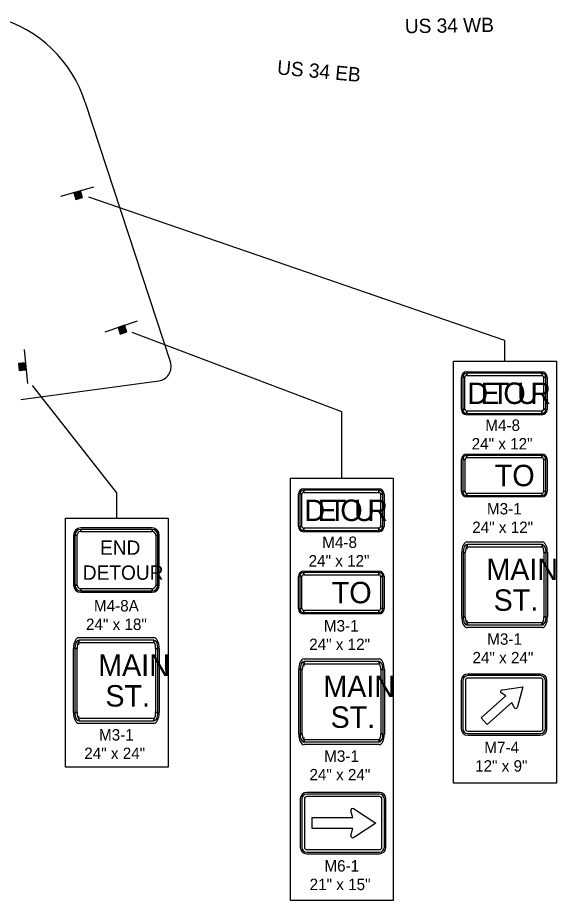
# Model space of a CAD drawing. Extents: x 10133 to 81668, y 6132 to 11018.
# Drawn here: x 11971 to 12349, y 8498 to 9117 of the extents above; entities that cross this region are included whole.
import ezdxf

# ---------------------------------------------------------------- set-up
doc = ezdxf.new("R2010")
doc.units = 0
for name, color, linetype in [('dsnTextFinalPlan', 7, 'Continuous'), ('Level 10', 7, 'Continuous'), ('Level 2', 7, 'Continuous'), ('Level 5', 7, 'Continuous')]:
    doc.layers.add(name, color=color, linetype=linetype)

msp = doc.modelspace()

# ---------------------------------------------------------------- linework, layer by layer
at = {"layer": 'dsnTextFinalPlan'}
for p, q in [((12001.09, 8991.94), (12024.18, 8998.48)), ((12015, 8995.5), (12010.31, 8994.18)), ((12010.37, 8993.94), (12015.07, 8995.27)), ((12015.13, 8995.05), (12010.44, 8993.72)), ((12010.5, 8993.5), (12015.19, 8994.83)), ((12015.25, 8994.64), (12010.55, 8993.31)), ((12010.6, 8993.14), (12015.29, 8994.47)), ((12015.37, 8994.18), (12010.68, 8992.85)), ((12010.74, 8992.63), (12015.44, 8993.96)), ((12015.49, 8993.77), (12010.79, 8992.46)), ((12010.87, 8992.18), (12015.57, 8993.5)), ((12015.66, 8993.19), (12010.96, 8991.86)), ((12011.07, 8991.5), (12015.76, 8992.83)), ((12015.81, 8992.64), (12011.11, 8991.33)), ((12011.22, 8990.96), (12015.91, 8992.28)), ((12015.96, 8992.1), (12011.27, 8990.77)), ((12011.35, 8990.51), (12016.04, 8991.84)), ((12016.09, 8991.65), (12011.4, 8990.32)), ((12011.47, 8990.05), (12016.17, 8991.38)), ((12032.17, 8896.87), (12054.89, 8904.6)), ((12045.88, 8901.15), (12041.26, 8899.58)), ((12041.34, 8899.35), (12045.96, 8900.92)), ((12046.03, 8900.7), (12041.41, 8899.13)), ((12041.49, 8898.91), (12046.1, 8900.49)), ((12046.17, 8900.3), (12041.55, 8898.73)), ((12041.61, 8898.56), (12046.23, 8900.13)), ((12046.32, 8899.85), (12041.7, 8898.28)), ((12041.78, 8898.06), (12046.39, 8899.63)), ((12046.46, 8899.45), (12041.84, 8897.89)), ((12041.93, 8897.61), (12046.55, 8899.18)), ((12046.65, 8898.87), (12042.04, 8897.3)), ((12042.16, 8896.95), (12046.77, 8898.52)), ((12046.84, 8898.33), (12042.22, 8896.78)), ((12042.34, 8896.42), (12046.96, 8897.98)), ((12047.02, 8897.81), (12042.4, 8896.23)), ((12042.49, 8895.97), (12047.11, 8897.54)), ((12047.17, 8897.36), (12042.55, 8895.78)), ((12042.64, 8895.52), (12047.26, 8897.09)), ((11975.3, 8884.55), (11977.56, 8860.65)), ((11971.57, 8874.67), (11972.03, 8869.82)), ((11972.3, 8869.84), (11971.84, 8874.7)), ((11972.04, 8874.72), (11972.5, 8869.86)), ((11972.77, 8869.89), (11972.32, 8874.74)), ((11972.51, 8874.76), (11972.95, 8869.91)), ((11973.33, 8869.94), (11972.89, 8874.8)), ((11973.07, 8874.82), (11973.52, 8869.96)), ((11973.9, 8870), (11973.44, 8874.85)), ((11973.77, 8874.88), (11974.22, 8870.03)), ((11974.5, 8870.05), (11974.06, 8874.91)), ((11974.24, 8874.93), (11974.7, 8870.07)), ((11974.93, 8870.09), (11974.47, 8874.95)), ((11974.76, 8874.98), (11975.22, 8870.12)), ((11975.4, 8870.14), (11974.94, 8874.99)), ((11975.13, 8875.01), (11975.59, 8870.16)), ((11975.82, 8870.18), (11975.36, 8875.03)), ((11975.59, 8875.05), (11976.05, 8870.2)), ((11976.29, 8870.22), (11975.84, 8875.08)), ((11972.93, 8849.28), (12069.69, 8862.39)), ((12337.44, 8656.85), (12286.47, 8656.85)), ((12281.89, 8652.27), (12281.89, 8618.48)), ((12342.02, 8618.48), (12342.02, 8652.27)), ((12286.47, 8613.9), (12337.44, 8613.9))]:
    msp.add_line(p, q, dxfattribs=at)
for points in [[(12018.16, 9057.63), (12018.16, 9057.63), (12077.85, 8875.41)], [(12312.56, 8876.29), (12312.56, 8890.73), (12020.7, 8991.36)], [(12198.2, 8794.21), (12198.2, 8840.64), (12051.02, 8896.35)], [(12040.25, 8766.11), (12040.25, 8784.03), (11981.11, 8859.25)], [(12319.03, 8633.29), (12317.4, 8636.8), (12300.08, 8621.52), (12295.92, 8626.23), (12313.25, 8641.51), (12309.95, 8643.54)], [(12310.74, 8645.71), (12325.1, 8647.78), (12321.24, 8633.81)]]:
    msp.add_lwpolyline(points, dxfattribs=at)
for points in [[(12014.92, 8995.77), (12010.2, 8994.43), (12011.54, 8989.71), (12016.26, 8991.05)], [(12045.79, 8901.41), (12041.14, 8899.83), (12042.72, 8895.18), (12047.37, 8896.77)], [(11976.57, 8870.25), (11976.11, 8875.14), (11971.22, 8874.67), (11971.68, 8869.79)], [(12276.52, 8876.29), (12348.59, 8876.29), (12348.59, 8580.2), (12276.52, 8580.2)], [(12276.52, 8876.29), (12348.59, 8876.29), (12348.59, 8580.2), (12276.52, 8580.2)], [(12162.17, 8794.21), (12234.23, 8794.21), (12234.23, 8498.11), (12162.17, 8498.11)], [(12162.17, 8794.21), (12234.23, 8794.21), (12234.23, 8498.11), (12162.17, 8498.11)], [(12004.21, 8766.11), (12076.28, 8766.11), (12076.28, 8591.52), (12004.21, 8591.52)], [(12004.21, 8766.11), (12076.28, 8766.11), (12076.28, 8591.52), (12004.21, 8591.52)]]:
    msp.add_lwpolyline(points, close=True, dxfattribs=at)
for centre, radius, start, end in [((11932.89, 9030.85), 89.37, 17.43569, 74.97168), ((12068.34, 8872.3), 10, 277.71379, 18.13661), ((12286.47, 8652.27), 4.58, 90, 180), ((12337.44, 8652.27), 4.58, 360, 90), ((12310.58, 8644.52), 1.16, 98.0346, 237.39274), ((12294.21, 8760.49), 115.96, 278.0346, 278.19506), ((12320.05, 8633.78), 1.14, 205.45459, 344.73406), ((12433.02, 8602.95), 115.96, 164.56669, 164.73406), ((12286.47, 8618.48), 4.58, 180, 270), ((12337.44, 8618.48), 4.58, 270, 0)]:
    msp.add_arc(centre, radius, start, end, dxfattribs=at)
at = {"layer": 'Level 10'}
for p, q in [((12285.73, 8868.78), (12338.34, 8868.78)), ((12285.73, 8866.28), (12285.73, 8867.84)), ((12338.34, 8867.84), (12338.34, 8866.28)), ((12281.97, 8842.48), (12281.97, 8865.03)), ((12282.91, 8865.03), (12284.48, 8865.03)), ((12339.6, 8865.03), (12341.16, 8865.03)), ((12342.1, 8865.03), (12342.1, 8842.48)), ((12284.48, 8842.48), (12282.91, 8842.48)), ((12285.73, 8839.66), (12285.73, 8841.23)), ((12338.34, 8841.23), (12338.34, 8839.66)), ((12341.16, 8842.48), (12339.6, 8842.48)), ((12338.34, 8838.72), (12285.73, 8838.72)), ((12285.78, 8811.1), (12338.39, 8811.1)), ((12285.78, 8808.59), (12285.78, 8810.16)), ((12338.39, 8810.16), (12338.39, 8808.59)), ((12282.02, 8784.79), (12282.02, 8807.34)), ((12282.96, 8807.34), (12284.52, 8807.34)), ((12339.64, 8807.34), (12341.21, 8807.34)), ((12342.15, 8807.34), (12342.15, 8784.79)), ((12171.38, 8786.7), (12223.99, 8786.7)), ((12171.38, 8784.19), (12171.38, 8785.76)), ((12223.99, 8785.76), (12223.99, 8784.19)), ((12284.52, 8784.79), (12282.96, 8784.79)), ((12341.21, 8784.79), (12339.64, 8784.79)), ((12167.62, 8760.39), (12167.62, 8782.94)), ((12168.56, 8782.94), (12170.12, 8782.94)), ((12225.24, 8782.94), (12226.81, 8782.94)), ((12227.75, 8782.94), (12227.75, 8760.39)), ((12285.78, 8781.97), (12285.78, 8783.54)), ((12338.39, 8781.03), (12285.78, 8781.03)), ((12338.39, 8783.54), (12338.39, 8781.97)), ((12170.12, 8760.39), (12168.56, 8760.39)), ((12226.81, 8760.39), (12225.24, 8760.39)), ((12009.94, 8754.26), (12009.94, 8719.19)), ((12010.94, 8754.26), (12010.94, 8719.19)), ((12012.44, 8754.26), (12010.94, 8754.26)), ((12010.94, 8754.26), (12012.44, 8754.26)), ((12012.44, 8719.19), (12012.44, 8754.26)), ((12065.06, 8759.27), (12014.95, 8759.27)), ((12014.95, 8756.77), (12014.95, 8758.27)), ((12065.06, 8758.27), (12014.95, 8758.27)), ((12014.95, 8758.27), (12014.95, 8756.77)), ((12014.95, 8756.77), (12065.06, 8756.77)), ((12065.06, 8756.77), (12065.06, 8758.27)), ((12065.06, 8758.27), (12065.06, 8756.77)), ((12067.56, 8754.26), (12069.06, 8754.26)), ((12067.56, 8754.26), (12067.56, 8719.19)), ((12069.06, 8754.26), (12067.56, 8754.26)), ((12069.06, 8719.19), (12069.06, 8754.26)), ((12070.07, 8719.19), (12070.07, 8754.26)), ((12171.38, 8757.57), (12171.38, 8759.14)), ((12223.99, 8756.63), (12171.38, 8756.63)), ((12223.99, 8759.14), (12223.99, 8757.57)), ((12285.97, 8749.51), (12338.58, 8749.51)), ((12285.97, 8744.5), (12285.97, 8747.64)), ((12338.58, 8747.64), (12338.58, 8746.07)), ((12282.21, 8696.9), (12282.21, 8742)), ((12283.15, 8742), (12284.71, 8742)), ((12339.83, 8742), (12341.4, 8742)), ((12342.34, 8742), (12342.34, 8696.9)), ((12171.42, 8729.01), (12224.03, 8729.01)), ((12167.66, 8702.7), (12167.66, 8725.25)), ((12168.6, 8725.25), (12170.17, 8725.25)), ((12171.42, 8726.5), (12171.42, 8728.07)), ((12224.03, 8728.07), (12224.03, 8726.5)), ((12225.29, 8725.25), (12226.85, 8725.25)), ((12227.79, 8725.25), (12227.79, 8702.7)), ((12010.94, 8719.19), (12012.44, 8719.19)), ((12012.44, 8719.19), (12010.94, 8719.19)), ((12065.06, 8716.68), (12014.95, 8716.68)), ((12014.95, 8716.68), (12014.95, 8715.18)), ((12014.95, 8715.18), (12014.95, 8716.68)), ((12065.06, 8716.68), (12065.06, 8715.18)), ((12065.06, 8715.18), (12065.06, 8716.68)), ((12067.56, 8719.19), (12069.06, 8719.19)), ((12069.06, 8719.19), (12067.56, 8719.19)), ((12014.95, 8715.18), (12065.06, 8715.18)), ((12014.95, 8714.18), (12065.06, 8714.18)), ((12170.17, 8702.7), (12168.6, 8702.7)), ((12171.42, 8699.89), (12171.42, 8701.45)), ((12224.03, 8698.95), (12171.42, 8698.95)), ((12224.03, 8701.45), (12224.03, 8699.89)), ((12226.85, 8702.7), (12225.29, 8702.7)), ((12284.71, 8696.9), (12283.15, 8696.9)), ((12285.97, 8691.27), (12285.97, 8694.4)), ((12338.58, 8692.83), (12338.58, 8691.27)), ((12341.4, 8696.9), (12339.83, 8696.9)), ((12338.58, 8689.39), (12285.97, 8689.39)), ((12013.66, 8682.37), (12066.27, 8682.37)), ((12013.66, 8677.36), (12013.66, 8680.49)), ((12066.27, 8680.49), (12066.27, 8678.92)), ((12009.9, 8629.75), (12009.9, 8674.85)), ((12010.84, 8674.85), (12012.41, 8674.85)), ((12067.52, 8674.85), (12069.09, 8674.85)), ((12070.03, 8674.85), (12070.03, 8629.75)), ((12171.61, 8667.43), (12224.22, 8667.43)), ((12171.61, 8662.42), (12171.61, 8665.55)), ((12224.22, 8665.55), (12224.22, 8663.98)), ((12167.85, 8614.81), (12167.85, 8659.91)), ((12168.79, 8659.91), (12170.36, 8659.91)), ((12225.48, 8659.91), (12227.04, 8659.91)), ((12227.98, 8659.91), (12227.98, 8614.81)), ((12337.44, 8655.71), (12286.47, 8655.71)), ((12283.03, 8652.27), (12283.03, 8618.48)), ((12284.75, 8652.27), (12284.75, 8618.48)), ((12337.44, 8653.99), (12286.47, 8653.99)), ((12339.15, 8618.48), (12339.15, 8652.27)), ((12340.87, 8618.48), (12340.87, 8652.27)), ((12012.41, 8629.75), (12010.84, 8629.75)), ((12013.66, 8624.12), (12013.66, 8627.25)), ((12066.27, 8625.68), (12066.27, 8624.12)), ((12069.09, 8629.75), (12067.52, 8629.75)), ((12066.27, 8622.24), (12013.66, 8622.24)), ((12170.36, 8614.81), (12168.79, 8614.81)), ((12171.61, 8609.18), (12171.61, 8612.31)), ((12227.04, 8614.81), (12225.48, 8614.81)), ((12286.47, 8616.76), (12337.44, 8616.76)), ((12286.47, 8615.05), (12337.44, 8615.05)), ((12224.22, 8607.3), (12171.61, 8607.3)), ((12224.22, 8610.74), (12224.22, 8609.18)), ((12168.96, 8569.19), (12168.96, 8535.4)), ((12170.1, 8569.19), (12170.1, 8535.4)), ((12171.82, 8569.19), (12171.82, 8535.4)), ((12224.51, 8573.77), (12173.54, 8573.77)), ((12224.51, 8572.63), (12173.54, 8572.63)), ((12224.51, 8570.91), (12173.54, 8570.91)), ((12226.22, 8535.4), (12226.22, 8569.19)), ((12227.94, 8535.4), (12227.94, 8569.19)), ((12229.09, 8535.4), (12229.09, 8569.19)), ((12173.54, 8533.69), (12224.51, 8533.69)), ((12173.54, 8531.97), (12224.51, 8531.97)), ((12173.54, 8530.82), (12224.51, 8530.82))]:
    msp.add_line(p, q, dxfattribs=at)
for points in [[(12338.34, 8867.84), (12285.73, 8867.84), (12285.73, 8866.28), (12338.34, 8866.28), (12338.34, 8867.84)], [(12282.91, 8865.03), (12282.91, 8842.48), (12284.48, 8842.48), (12284.48, 8865.03), (12282.91, 8865.03)], [(12341.16, 8842.48), (12341.16, 8865.03), (12339.6, 8865.03), (12339.6, 8842.48), (12341.16, 8842.48)], [(12285.73, 8839.66), (12338.34, 8839.66), (12338.34, 8841.23), (12285.73, 8841.23), (12285.73, 8839.66)], [(12338.39, 8810.16), (12285.78, 8810.16), (12285.78, 8808.59), (12338.39, 8808.59), (12338.39, 8810.16)], [(12282.96, 8807.34), (12282.96, 8784.79), (12284.52, 8784.79), (12284.52, 8807.34), (12282.96, 8807.34)], [(12341.21, 8784.79), (12341.21, 8807.34), (12339.64, 8807.34), (12339.64, 8784.79), (12341.21, 8784.79)], [(12223.99, 8785.76), (12171.38, 8785.76), (12171.38, 8784.19), (12223.99, 8784.19), (12223.99, 8785.76)], [(12168.56, 8782.94), (12168.56, 8760.39), (12170.12, 8760.39), (12170.12, 8782.94), (12168.56, 8782.94)], [(12226.81, 8760.39), (12226.81, 8782.94), (12225.24, 8782.94), (12225.24, 8760.39), (12226.81, 8760.39)], [(12285.78, 8781.97), (12338.39, 8781.97), (12338.39, 8783.54), (12285.78, 8783.54), (12285.78, 8781.97)], [(12171.38, 8757.57), (12223.99, 8757.57), (12223.99, 8759.14), (12171.38, 8759.14), (12171.38, 8757.57)], [(12338.58, 8747.64), (12285.97, 8747.64), (12285.97, 8746.07), (12338.58, 8746.07), (12338.58, 8747.64)], [(12283.15, 8742), (12283.15, 8696.9), (12284.71, 8696.9), (12284.71, 8742), (12283.15, 8742)], [(12341.4, 8696.9), (12341.4, 8742), (12339.83, 8742), (12339.83, 8696.9), (12341.4, 8696.9)], [(12168.6, 8725.25), (12168.6, 8702.7), (12170.17, 8702.7), (12170.17, 8725.25), (12168.6, 8725.25)], [(12224.03, 8728.07), (12171.42, 8728.07), (12171.42, 8726.5), (12224.03, 8726.5), (12224.03, 8728.07)], [(12226.85, 8702.7), (12226.85, 8725.25), (12225.29, 8725.25), (12225.29, 8702.7), (12226.85, 8702.7)], [(12171.42, 8699.89), (12224.03, 8699.89), (12224.03, 8701.45), (12171.42, 8701.45), (12171.42, 8699.89)], [(12285.97, 8691.27), (12338.58, 8691.27), (12338.58, 8692.83), (12285.97, 8692.83), (12285.97, 8691.27)], [(12066.27, 8680.49), (12013.66, 8680.49), (12013.66, 8678.92), (12066.27, 8678.92), (12066.27, 8680.49)], [(12010.84, 8674.85), (12010.84, 8629.75), (12012.41, 8629.75), (12012.41, 8674.85), (12010.84, 8674.85)], [(12069.09, 8629.75), (12069.09, 8674.85), (12067.52, 8674.85), (12067.52, 8629.75), (12069.09, 8629.75)], [(12224.22, 8665.55), (12171.61, 8665.55), (12171.61, 8663.98), (12224.22, 8663.98), (12224.22, 8665.55)], [(12168.79, 8659.91), (12168.79, 8614.81), (12170.36, 8614.81), (12170.36, 8659.91), (12168.79, 8659.91)], [(12227.04, 8614.81), (12227.04, 8659.91), (12225.48, 8659.91), (12225.48, 8614.81), (12227.04, 8614.81)], [(12013.66, 8624.12), (12066.27, 8624.12), (12066.27, 8625.68), (12013.66, 8625.68), (12013.66, 8624.12)], [(12171.61, 8609.18), (12224.22, 8609.18), (12224.22, 8610.74), (12171.61, 8610.74), (12171.61, 8609.18)]]:
    msp.add_lwpolyline(points, close=True, dxfattribs=at)
for points in [[(12206.94, 8562.12), (12221.93, 8552.3), (12206.94, 8542.51)], [(12204.47, 8543.84), (12205.84, 8548.42), (12177.31, 8548.42), (12177.31, 8556.17), (12205.84, 8556.17), (12204.44, 8560.75)]]:
    msp.add_lwpolyline(points, dxfattribs=at)
for centre, radius, start, end in [((12285.73, 8865.03), 3.76, 90, 180), ((12285.73, 8865.03), 2.82, 90.00021, 179.99985), ((12285.73, 8865.03), 1.25, 90.00021, 179.99985), ((12338.34, 8865.03), 3.76, 0, 90), ((12338.34, 8865.03), 2.82, 0, 90.00021), ((12338.34, 8865.03), 1.25, 0, 90.00021), ((12285.73, 8842.48), 3.76, 180, 270), ((12285.73, 8842.48), 2.82, 179.99985, 270.00006), ((12285.73, 8842.48), 1.25, 179.99985, 270.00006), ((12338.34, 8842.48), 2.82, 270.00006, 0.00027), ((12338.34, 8842.48), 1.25, 270.00006, 0.00027), ((12338.34, 8842.48), 3.76, 270, 359.99112), ((12285.78, 8807.34), 3.76, 90, 180), ((12285.78, 8807.34), 2.82, 90.00021, 179.99985), ((12338.39, 8807.34), 3.76, 0, 90), ((12338.39, 8807.34), 2.82, 0, 90.00021), ((12285.78, 8807.34), 1.25, 90.00021, 179.99985), ((12338.39, 8807.34), 1.25, 0, 90.00021), ((12171.38, 8782.94), 3.76, 90, 180), ((12171.38, 8782.94), 2.82, 90.00021, 179.99985), ((12223.99, 8782.94), 3.76, 0, 90), ((12223.99, 8782.94), 2.82, 0, 90.00021), ((12285.78, 8784.79), 3.76, 180, 270), ((12285.78, 8784.79), 2.82, 179.99985, 270.00006), ((12285.78, 8784.79), 1.25, 179.99985, 270.00006), ((12338.39, 8784.79), 2.82, 270.00006, 0.00027), ((12338.39, 8784.79), 1.25, 270.00006, 0.00027), ((12338.39, 8784.79), 3.76, 270, 359.99112), ((12171.38, 8782.94), 1.25, 90.00021, 179.99985), ((12223.99, 8782.94), 1.25, 0, 90.00021), ((12171.38, 8760.39), 3.76, 180, 270), ((12171.38, 8760.39), 2.82, 179.99985, 270.00006), ((12171.38, 8760.39), 1.25, 179.99985, 270.00006), ((12223.99, 8760.39), 2.82, 270.00006, 0.00027), ((12223.99, 8760.39), 1.25, 270.00006, 0.00027), ((12223.99, 8760.39), 3.76, 270, 359.99112), ((12014.95, 8754.26), 5.01, 90, 180), ((12014.95, 8754.26), 4.01, 90, 180), ((12014.95, 8754.26), 2.51, 90, 180), ((12065.06, 8754.26), 5.01, 0, 90), ((12065.06, 8754.26), 4.01, 0, 90), ((12065.06, 8754.26), 2.51, 0, 90), ((12171.42, 8725.25), 3.76, 90, 180), ((12224.03, 8725.25), 3.76, 0, 90), ((12171.42, 8725.25), 2.82, 90.00021, 179.99985), ((12171.42, 8725.25), 1.25, 90.00021, 179.99985), ((12224.03, 8725.25), 2.82, 0, 90.00021), ((12224.03, 8725.25), 1.25, 0, 90.00021), ((12014.95, 8719.19), 5.01, 180, 270), ((12014.95, 8719.19), 4.01, 180, 270), ((12014.95, 8719.19), 2.51, 180, 270), ((12065.06, 8719.19), 2.51, 270, 0), ((12065.06, 8719.19), 4.01, 270, 360), ((12065.06, 8719.19), 5.01, 270, 0), ((12171.42, 8702.7), 3.76, 180, 270), ((12171.42, 8702.7), 2.82, 179.99985, 270.00006), ((12171.42, 8702.7), 1.25, 179.99985, 270.00006), ((12224.03, 8702.7), 2.82, 270.00006, 0.00027), ((12224.03, 8702.7), 1.25, 270.00006, 0.00027), ((12224.03, 8702.7), 3.76, 270, 359.99112), ((12286.47, 8652.27), 3.44, 90, 180), ((12337.44, 8652.27), 3.44, 0, 90), ((12286.47, 8652.27), 1.72, 90, 180), ((12337.44, 8652.27), 1.72, 0, 90), ((12286.47, 8618.48), 3.44, 180, 270), ((12286.47, 8618.48), 1.72, 180, 270), ((12337.44, 8618.48), 3.44, 270, 360), ((12337.44, 8618.48), 1.72, 270, 0), ((12173.54, 8569.19), 4.58, 90, 180), ((12173.54, 8569.19), 3.44, 90, 180), ((12173.54, 8569.19), 1.72, 90, 180), ((12224.51, 8569.19), 4.58, 360, 90), ((12224.51, 8569.19), 3.44, 0, 90), ((12224.51, 8569.19), 1.72, 0, 90), ((12205.82, 8561.14), 1.43, 56.61094, 195.96908), ((12285.39, 8681.87), 143.16, 236.61094, 236.7714), ((12205.82, 8543.45), 1.4, 164.03092, 303.3104), ((12285.21, 8422.64), 143.16, 123.14303, 123.31039), ((12173.54, 8535.4), 4.58, 180, 270), ((12173.54, 8535.4), 3.44, 180, 270), ((12173.54, 8535.4), 1.72, 180, 270), ((12224.51, 8535.4), 4.58, 270, 0), ((12224.51, 8535.4), 3.44, 270, 360), ((12224.51, 8535.4), 1.72, 270, 0)]:
    msp.add_arc(centre, radius, start, end, dxfattribs=at)
for centre, major_axis, ratio, start_param, end_param in [((12285.97, 8742), (0, 7.52), 0.5, 6.283185, 7.853982), ((12285.97, 8742), (0, 5.64), 0.5, 0.000004, 1.570794), ((12338.58, 8742), (0, 7.52), 0.5, 4.712389, 6.283185), ((12338.58, 8742), (0, 5.64), 0.5, 4.712389, 6.283189), ((12285.97, 8742), (0, 4.07), 0.307692, 0.000004, 1.570794), ((12338.58, 8742), (0, 4.07), 0.307692, 4.712389, 6.283189), ((12285.97, 8696.9), (0, 7.52), 0.5, 1.570796, 3.141593), ((12285.97, 8696.9), (0, 5.64), 0.5, 1.570794, 3.141594), ((12285.97, 8696.9), (0, 4.07), 0.307692, 1.570794, 3.141594), ((12338.58, 8696.9), (0, 5.64), 0.5, 3.141594, 4.712394), ((12338.58, 8696.9), (0, 4.07), 0.307692, 3.141594, 4.712394), ((12338.58, 8696.9), (0, 7.52), 0.5, 3.141593, 4.712234), ((12013.66, 8674.85), (0, 7.52), 0.5, 6.283185, 7.853982), ((12013.66, 8674.85), (0, 5.64), 0.5, 0.000004, 1.570794), ((12066.27, 8674.85), (0, 7.52), 0.5, 4.712389, 6.283185), ((12066.27, 8674.85), (0, 5.64), 0.5, 4.712389, 6.283189), ((12013.66, 8674.85), (0, 4.07), 0.307692, 0.000004, 1.570794), ((12066.27, 8674.85), (0, 4.07), 0.307692, 4.712389, 6.283189), ((12171.61, 8659.91), (0, 7.52), 0.5, 6.283185, 7.853982), ((12224.22, 8659.91), (0, 7.52), 0.5, 4.712389, 6.283185), ((12171.61, 8659.91), (0, 5.64), 0.5, 0.000004, 1.570794), ((12171.61, 8659.91), (0, 4.07), 0.307692, 0.000004, 1.570794), ((12224.22, 8659.91), (0, 5.64), 0.5, 4.712389, 6.283189), ((12224.22, 8659.91), (0, 4.07), 0.307692, 4.712389, 6.283189), ((12013.66, 8629.75), (0, 7.52), 0.5, 1.570796, 3.141593), ((12013.66, 8629.75), (0, 5.64), 0.5, 1.570794, 3.141594), ((12013.66, 8629.75), (0, 4.07), 0.307692, 1.570794, 3.141594), ((12066.27, 8629.75), (0, 5.64), 0.5, 3.141594, 4.712394), ((12066.27, 8629.75), (0, 4.07), 0.307692, 3.141594, 4.712394), ((12066.27, 8629.75), (0, 7.52), 0.5, 3.141593, 4.712234), ((12171.61, 8614.81), (0, 7.52), 0.5, 1.570796, 3.141593), ((12171.61, 8614.81), (0, 5.64), 0.5, 1.570794, 3.141594), ((12171.61, 8614.81), (0, 4.07), 0.307692, 1.570794, 3.141594), ((12224.22, 8614.81), (0, 5.64), 0.5, 3.141594, 4.712394), ((12224.22, 8614.81), (0, 4.07), 0.307692, 3.141594, 4.712394), ((12224.22, 8614.81), (0, 7.52), 0.5, 3.141593, 4.712234)]:
    msp.add_ellipse(centre, major_axis=major_axis, ratio=ratio, start_param=start_param, end_param=end_param, dxfattribs=at)

# ---------------------------------------------------------------- texts
for s, height, p in [('D', 15.03, (12286.22, 8846.24)), ('E', 15.03, (12295.45, 8846.24)), ('T', 15.03, (12303.23, 8846.24)), ('O', 15.03, (12311.44, 8846.24)), ('U', 15.03, (12321.03, 8846.24)), ('R', 15.03, (12330.27, 8846.24)), ('TO', 15.032, (12305.44, 8788.55)), ('D', 15.03, (12171.86, 8764.15)), ('E', 15.03, (12181.1, 8764.15)), ('T', 15.03, (12188.88, 8764.15)), ('O', 15.03, (12197.08, 8764.15)), ('U', 15.03, (12206.68, 8764.15)), ('R', 15.03, (12215.91, 8764.15)), ('END', 10.021, (12028.47, 8740.48)), ('MAIN', 15.032, (12299.54, 8722.7)), ('DETOUR', 10.021, (12016.43, 8722.95)), ('TO', 15.032, (12191.09, 8706.46)), ('ST.', 15.032, (12304.59, 8701.17)), ('MAIN', 15.032, (12027.23, 8655.55)), ('MAIN', 15.032, (12185.18, 8640.61)), ('ST.', 15.032, (12032.28, 8634.02)), ('ST.', 15.032, (12190.23, 8619.08))]:
    msp.add_text(s, height=height, dxfattribs=at).set_placement(p)
at = {"layer": 'Level 2'}
for s, rotation, p in [('US 34 WB', 0.90078, (12242.43, 9106.22)), ('US 34 EB', 354.77529, (12152.41, 9077.43))]:
    msp.add_text(s, height=10, rotation=rotation, dxfattribs=at).set_placement(p)
at = {"layer": 'Level 5'}
for s, p in [('M4-8', (12298.74, 8827.33)), ('24" x 12"', (12289.19, 8814.33)), ('M3-1', (12299.9, 8768.74)), ('24" x 12"', (12289.57, 8755.74)), ('M4-8', (12184.38, 8745.25)), ('24" x 12"', (12174.83, 8732.25)), ('M4-8A', (12024.23, 8700.7)), ('24" x 18"', (12018.66, 8687.7)), ('M3-1', (12185.55, 8686.65)), ('24" x 12"', (12175.21, 8673.65)), ('M3-1', (12300.09, 8677.34)), ('24" x 24"', (12289.76, 8664.34)), ('M3-1', (12027.79, 8610.2)), ('24" x 24"', (12017.45, 8597.2)), ('M7-4', (12298.06, 8601.39)), ('M3-1', (12185.74, 8595.25)), ('12" x 9"', (12291.59, 8588.39)), ('24" x 24"', (12175.41, 8582.25)), ('M6-1', (12185.89, 8518.31)), ('21" x 15"', (12175.55, 8505.31))]:
    msp.add_text(s, height=8, dxfattribs=at).set_placement(p)

doc.saveas('drawing.dxf')
